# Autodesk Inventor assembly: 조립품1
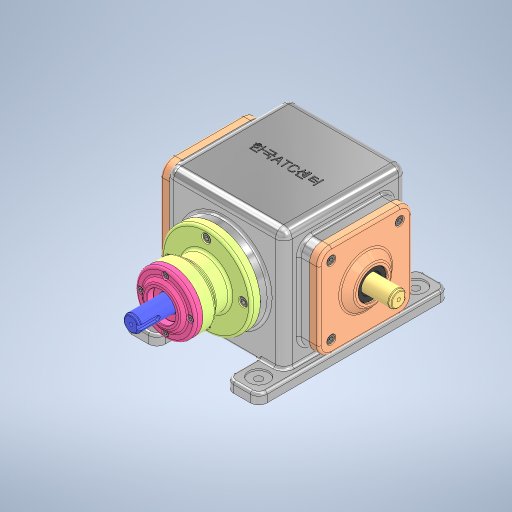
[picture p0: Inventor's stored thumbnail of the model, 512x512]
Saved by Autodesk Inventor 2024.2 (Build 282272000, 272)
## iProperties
Created: 2026-01
Part Number: 조립품1
Document SubType Name: Assembly
Designer: home
Author: home
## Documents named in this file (17)
- C:\Users\home\Desktop\760103V1013\조립품1.iam
- C:\Users\home\Desktop\760103V1013\부품1.ipt
- C:\Users\home\Desktop\760103V1013\테이퍼 롤러 베어링 30204K\테이퍼 롤러 베어링 30204K.ipt
- C:\Users\home\Desktop\760103V1013\6각 구멍붙이 볼트 M4x10\6각 구멍붙이 볼트 M4x10.ipt
- C:\Users\home\Desktop\760103V1013\6각 구멍붙이 볼트 M6x12\6각 구멍붙이 볼트 M6x12.ipt
- C:\Users\home\Desktop\760103V1013\구동축\구동축.ipt
- C:\Users\home\Desktop\760103V1013\베벨 기어(구동)\베벨 기어(구동).ipt
- C:\Users\home\Desktop\760103V1013\베벨 기어(종동)\베벨 기어(종동).ipt
- C:\Users\home\Desktop\760103V1013\베어링 하우징\베어링 하우징.ipt
- C:\Users\home\Desktop\760103V1013\엔드캡\엔드캡.ipt
- C:\Users\home\Desktop\760103V1013\오일 실 20 35 8\오일 실 20 35 8.ipt
- C:\Users\home\Desktop\760103V1013\종동축\종동축.ipt
- C:\Users\home\Desktop\760103V1013\측면 커버\측면 커버.ipt
- C:\Users\home\Desktop\760103V1013\칼라\칼라.ipt
- C:\Users\home\Desktop\760103V1013\평행 키 6x6x18\평행 키 6x6x18.ipt
- C:\Users\home\Desktop\760103V1013\하우징 커버\하우징 커버.ipt
- C:\Users\home\Desktop\760103V1013\6각 구멍붙이 볼트 M6x12\6각 구멍붙이 볼트 M6x12_MIR.ipt
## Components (19 placed, 5 different names)
1. 6각 구멍붙이 볼트 M4x10:1
2. 6각 구멍붙이 볼트 M6x12:1
3. 구동축:1
4. 하우징 커버:1
5. 6각 구멍붙이 볼트 M6x12:2 — 각도:1
6. 6각 구멍붙이 볼트 M6x12:3 — 각도:2
7. 6각 구멍붙이 볼트 M6x12:4
8. 6각 구멍붙이 볼트 M6x12:5 — 각도:3
9. 6각 구멍붙이 볼트 M6x12_MIR:1
10. 6각 구멍붙이 볼트 M6x12_MIR:2
11. 6각 구멍붙이 볼트 M6x12_MIR:3
12. 6각 구멍붙이 볼트 M6x12_MIR:4
13. 6각 구멍붙이 볼트 M6x12_MIR:5
14. 6각 구멍붙이 볼트 M6x12_MIR:6
15. 6각 구멍붙이 볼트 M6x12_MIR:7
16. 6각 구멍붙이 볼트 M6x12_MIR:8
17. 6각 구멍붙이 볼트 M4x10:2
18. 6각 구멍붙이 볼트 M4x10:3
19. 6각 구멍붙이 볼트 M4x10:4
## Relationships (3: Angle 3)
- 각도:1 [Angle]: 6각 구멍붙이 볼트 M6x12:2
- 각도:2 [Angle]: 6각 구멍붙이 볼트 M6x12:3
- 각도:3 [Angle]: 6각 구멍붙이 볼트 M6x12:5
